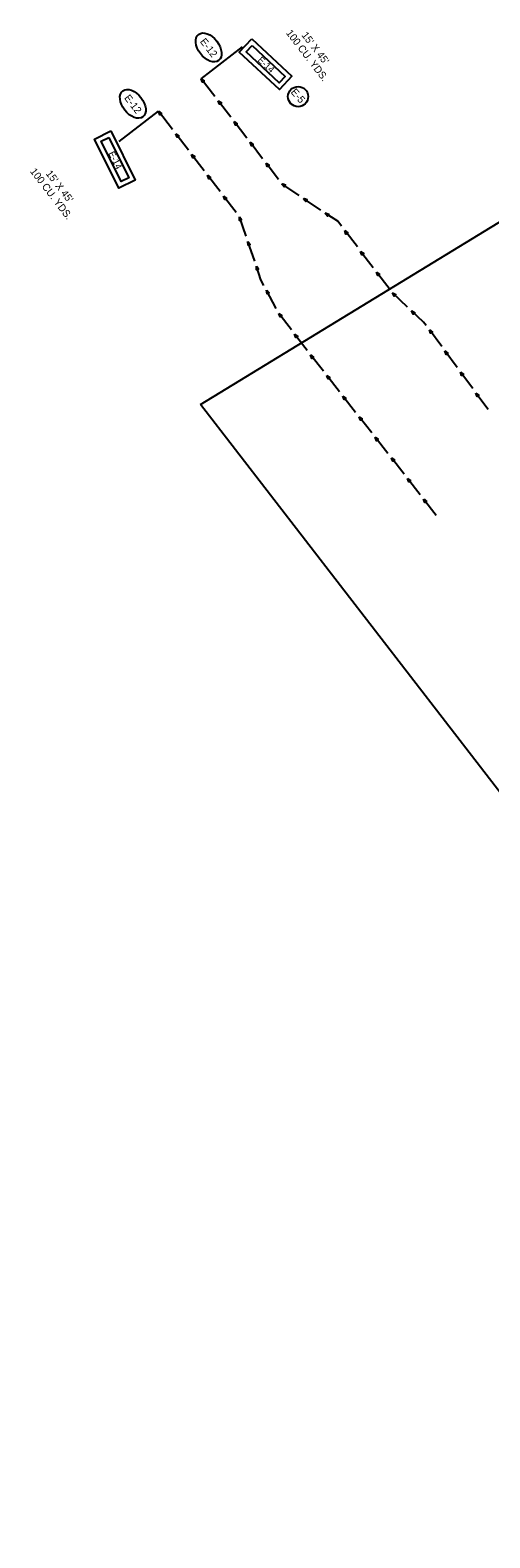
# Model space of a CAD drawing. Extents: x 881727 to 890277, y 1562105 to 1567179.
# Drawn here: x 883424 to 883800, y 1565042 to 1566277 of the extents above; entities that cross this region are included whole.
import ezdxf

# ---------------------------------------------------------------- set-up
doc = ezdxf.new("R2010")
doc.units = 0
for name, color, linetype in [('22', 7, 'Continuous'), ('R_Axis', 7, 'Continuous'), ('R_Proposed Const Limits_Cut', 7, 'Continuous'), ('R_Water', 7, 'Continuous')]:
    doc.layers.add(name, color=color, linetype=linetype)

msp = doc.modelspace()

# ---------------------------------------------------------------- linework, layer by layer
at = {"layer": '22'}
msp.add_lwpolyline([(883563.3, 1565970.3), (883827.9, 1566132), (884540.8, 1565246.7), (884279.1, 1565042.3)], close=True, dxfattribs=at)
at = {"layer": 'R_Proposed Const Limits_Cut'}
for p, q in [((883563.9, 1566237.1), (883597.7, 1566263.1)), ((883565.3, 1566234.6), (883564.2, 1566236.5)), ((883565.1, 1566234.4), (883564.2, 1566236.4)), ((883565.4, 1566234.7), (883564.3, 1566236.5)), ((883566, 1566235.1), (883564.4, 1566236.6)), ((883565.8, 1566235), (883564.4, 1566236.6)), ((883566.1, 1566235.2), (883564.5, 1566236.6)), ((883579, 1566216.3), (883578.1, 1566218.3)), ((883579.4, 1566216.5), (883578.2, 1566218.3)), ((883579.2, 1566216.4), (883578.2, 1566218.3)), ((883579.9, 1566216.9), (883578.3, 1566218.4)), ((883579.7, 1566216.8), (883578.3, 1566218.4)), ((883580.1, 1566217.1), (883578.4, 1566218.5)), ((883496.7, 1566185.6), (883528.9, 1566210.4)), ((883530.3, 1566207.8), (883529.3, 1566209.7)), ((883530.2, 1566207.7), (883529.3, 1566209.7)), ((883530.5, 1566207.9), (883529.4, 1566209.7)), ((883531.2, 1566208.5), (883529.5, 1566209.9)), ((883531, 1566208.3), (883529.5, 1566209.8)), ((883530.9, 1566208.2), (883529.5, 1566209.8)), ((883544.9, 1566189.9), (883543.5, 1566191.4)), ((883545.3, 1566190.1), (883543.6, 1566191.5)), ((883545.1, 1566190), (883543.6, 1566191.5)), ((883592, 1566199.3), (883591.1, 1566201.3)), ((883592.4, 1566199.5), (883591.2, 1566201.3)), ((883592.2, 1566199.4), (883591.2, 1566201.3)), ((883592.8, 1566199.8), (883591.3, 1566201.4)), ((883593.1, 1566200.1), (883591.4, 1566201.5)), ((883592.9, 1566199.9), (883591.4, 1566201.4)), ((883544.2, 1566189.3), (883543.3, 1566191.3)), ((883544.6, 1566189.6), (883543.4, 1566191.4)), ((883544.4, 1566189.5), (883543.4, 1566191.3)), ((883605.3, 1566182.4), (883604.2, 1566184.3)), ((883605.1, 1566182.3), (883604.2, 1566184.3)), ((883605.4, 1566182.5), (883604.3, 1566184.3)), ((883606.1, 1566183.1), (883604.4, 1566184.5)), ((883606, 1566182.9), (883604.4, 1566184.4)), ((883605.8, 1566182.8), (883604.4, 1566184.4)), ((883557.3, 1566172.3), (883556.3, 1566174.3)), ((883557.4, 1566172.5), (883556.4, 1566174.3)), ((883558, 1566172.9), (883556.5, 1566174.4)), ((883557.6, 1566172.6), (883556.5, 1566174.4)), ((883558.3, 1566173.1), (883556.6, 1566174.5)), ((883558.1, 1566173), (883556.6, 1566174.5)), ((883618.3, 1566165.4), (883617.2, 1566167.3)), ((883618.1, 1566165.3), (883617.2, 1566167.3)), ((883618.5, 1566165.5), (883617.3, 1566167.3)), ((883619, 1566165.9), (883617.4, 1566167.4)), ((883618.8, 1566165.8), (883617.4, 1566167.4)), ((883619.2, 1566166.1), (883617.5, 1566167.5)), ((883570.5, 1566155.5), (883569.4, 1566157.4)), ((883570.3, 1566155.3), (883569.4, 1566157.3)), ((883570.6, 1566155.6), (883569.5, 1566157.4)), ((883571.2, 1566156), (883569.6, 1566157.5)), ((883571, 1566155.9), (883569.6, 1566157.5)), ((883571.3, 1566156.1), (883569.7, 1566157.5)), ((883631.9, 1566148.8), (883630.4, 1566150.4)), ((883632.2, 1566149.2), (883630.5, 1566150.5)), ((883632, 1566149), (883630.5, 1566150.4)), ((883632.7, 1566149.9), (883630.6, 1566150.7)), ((883632.5, 1566149.7), (883630.6, 1566150.6)), ((883632.4, 1566149.5), (883630.6, 1566150.6)), ((883583.3, 1566138.3), (883582.4, 1566140.3)), ((883583.7, 1566138.6), (883582.5, 1566140.4)), ((883583.5, 1566138.5), (883582.5, 1566140.4)), ((883584.2, 1566139), (883582.6, 1566140.5)), ((883584, 1566138.9), (883582.6, 1566140.5)), ((883584.4, 1566139.1), (883582.7, 1566140.5)), ((883649.6, 1566136.7), (883648.1, 1566138.3)), ((883649.9, 1566137.1), (883648.2, 1566138.4)), ((883649.7, 1566136.9), (883648.2, 1566138.4)), ((883650.4, 1566137.8), (883648.3, 1566138.6)), ((883650.2, 1566137.7), (883648.3, 1566138.6)), ((883650.1, 1566137.5), (883648.3, 1566138.5)), ((883595.4, 1566121.1), (883595.2, 1566123.3)), ((883595.8, 1566121.2), (883595.3, 1566123.3)), ((883595.6, 1566121.2), (883595.3, 1566123.3)), ((883596.3, 1566121.4), (883595.4, 1566123.3)), ((883596.7, 1566121.5), (883595.5, 1566123.4)), ((883596.5, 1566121.5), (883595.5, 1566123.4)), ((883667.5, 1566125), (883665.9, 1566126.4)), ((883667.4, 1566124.8), (883665.9, 1566126.4)), ((883668, 1566125.7), (883666, 1566126.6)), ((883667.9, 1566125.5), (883666, 1566126.5)), ((883667.6, 1566125.2), (883666, 1566126.4)), ((883668.1, 1566125.9), (883666.1, 1566126.7)), ((883682.7, 1566110.2), (883681.6, 1566112.1)), ((883682.5, 1566110.1), (883681.6, 1566112)), ((883682.8, 1566110.3), (883681.7, 1566112.1)), ((883683.4, 1566110.7), (883681.8, 1566112.2)), ((883683.2, 1566110.6), (883681.8, 1566112.2)), ((883683.5, 1566110.9), (883681.9, 1566112.3)), ((883602.4, 1566100.9), (883602.2, 1566103)), ((883602.9, 1566101), (883602.3, 1566103.1)), ((883602.7, 1566100.9), (883602.3, 1566103)), ((883603.3, 1566101.2), (883602.4, 1566103.1)), ((883603.7, 1566101.3), (883602.5, 1566103.2)), ((883603.5, 1566101.2), (883602.5, 1566103.1)), ((883695.5, 1566093.1), (883694.6, 1566095)), ((883695.9, 1566093.3), (883694.7, 1566095.1)), ((883695.7, 1566093.2), (883694.7, 1566095.1)), ((883696.4, 1566093.7), (883694.8, 1566095.2)), ((883696.2, 1566093.6), (883694.8, 1566095.2)), ((883696.6, 1566093.9), (883694.9, 1566095.3)), ((883609.3, 1566080.6), (883609.1, 1566082.8)), ((883609.6, 1566080.7), (883609.2, 1566082.8)), ((883609.8, 1566080.7), (883609.3, 1566082.8)), ((883610.4, 1566080.9), (883609.4, 1566082.9)), ((883610.2, 1566080.9), (883609.4, 1566082.8)), ((883610.6, 1566081), (883609.5, 1566082.9)), ((883708.5, 1566076.1), (883707.6, 1566078)), ((883708.9, 1566076.3), (883707.7, 1566078.1)), ((883708.7, 1566076.2), (883707.7, 1566078.1)), ((883709.3, 1566076.6), (883707.8, 1566078.2)), ((883709.6, 1566076.9), (883707.9, 1566078.3)), ((883709.4, 1566076.7), (883707.9, 1566078.2)), ((883618.1, 1566061), (883617.5, 1566063.1)), ((883618.5, 1566061.2), (883617.6, 1566063.2)), ((883618.3, 1566061.1), (883617.6, 1566063.1)), ((883618.8, 1566061.4), (883617.7, 1566063.2)), ((883619.2, 1566061.6), (883617.8, 1566063.3)), ((883619, 1566061.5), (883617.8, 1566063.2)), ((883722.1, 1566059.4), (883720.8, 1566061.1)), ((883722, 1566059.3), (883720.8, 1566061.1)), ((883722.6, 1566059.9), (883720.9, 1566061.3)), ((883722.3, 1566059.6), (883720.9, 1566061.2)), ((883722.9, 1566060.2), (883721, 1566061.4)), ((883722.7, 1566060.1), (883721, 1566061.3)), ((883628.7, 1566042.4), (883627.7, 1566044.3)), ((883628.6, 1566042.3), (883627.7, 1566044.2)), ((883628.9, 1566042.5), (883627.8, 1566044.3)), ((883629.6, 1566043.1), (883627.9, 1566044.5)), ((883629.5, 1566042.9), (883627.9, 1566044.4)), ((883629.3, 1566042.8), (883627.9, 1566044.4)), ((883737.4, 1566044.4), (883736.2, 1566046.3)), ((883737.7, 1566044.7), (883736.3, 1566046.4)), ((883737.5, 1566044.6), (883736.3, 1566046.3)), ((883738.2, 1566045.2), (883736.4, 1566046.5)), ((883738, 1566045.1), (883736.4, 1566046.4)), ((883738.3, 1566045.4), (883736.5, 1566046.5)), ((883752.8, 1566029.5), (883751.1, 1566030.9)), ((883641.5, 1566025.2), (883640.6, 1566027.2)), ((883641.9, 1566025.5), (883640.7, 1566027.2)), ((883641.7, 1566025.3), (883640.7, 1566027.2)), ((883642.2, 1566025.7), (883640.8, 1566027.3)), ((883642.6, 1566026), (883640.9, 1566027.4)), ((883642.4, 1566025.9), (883640.9, 1566027.4)), ((883751.7, 1566028.7), (883750.8, 1566030.7)), ((883752.1, 1566029), (883750.9, 1566030.8)), ((883751.9, 1566028.8), (883750.9, 1566030.7)), ((883752.4, 1566029.2), (883751, 1566030.8)), ((883752.6, 1566029.4), (883751.1, 1566030.9)), ((883654.6, 1566008.2), (883653.6, 1566010.2)), ((883654.9, 1566008.5), (883653.7, 1566010.2)), ((883654.7, 1566008.3), (883653.7, 1566010.2)), ((883655.3, 1566008.7), (883653.8, 1566010.3)), ((883655.6, 1566009), (883653.9, 1566010.4)), ((883655.4, 1566008.9), (883653.9, 1566010.3)), ((883764.4, 1566011.5), (883763.5, 1566013.5)), ((883764.8, 1566011.7), (883763.6, 1566013.5)), ((883764.6, 1566011.6), (883763.6, 1566013.5)), ((883765.1, 1566012), (883763.7, 1566013.6)), ((883765.5, 1566012.3), (883763.8, 1566013.7)), ((883765.3, 1566012.1), (883763.8, 1566013.6)), ((883777.1, 1565994.2), (883776.2, 1565996.2)), ((883777.5, 1565994.5), (883776.3, 1565996.3)), ((883777.3, 1565994.4), (883776.3, 1565996.3)), ((883777.8, 1565994.8), (883776.4, 1565996.4)), ((883778.2, 1565995), (883776.5, 1565996.4)), ((883778, 1565994.9), (883776.5, 1565996.4)), ((883668, 1565991.5), (883666.9, 1565993.4)), ((883667.8, 1565991.4), (883666.9, 1565993.3)), ((883668.1, 1565991.6), (883667, 1565993.4)), ((883668.8, 1565992.2), (883667.1, 1565993.5)), ((883668.7, 1565992), (883667.1, 1565993.5)), ((883668.5, 1565991.9), (883667.1, 1565993.5)), ((883681.2, 1565974.6), (883680.1, 1565976.5)), ((883681, 1565974.5), (883680.1, 1565976.5)), ((883681.4, 1565974.8), (883680.2, 1565976.5)), ((883681.9, 1565975.2), (883680.3, 1565976.7)), ((883681.7, 1565975.1), (883680.3, 1565976.6)), ((883682.1, 1565975.3), (883680.4, 1565976.7)), ((883789.8, 1565977), (883788.9, 1565979)), ((883790.2, 1565977.2), (883789, 1565979)), ((883790, 1565977.1), (883789, 1565979)), ((883790.5, 1565977.5), (883789.1, 1565979.1)), ((883790.9, 1565977.8), (883789.2, 1565979.2)), ((883790.7, 1565977.6), (883789.2, 1565979.1)), ((883694.2, 1565957.7), (883693.3, 1565959.6)), ((883694.6, 1565957.9), (883693.4, 1565959.7)), ((883694.4, 1565957.8), (883693.4, 1565959.7)), ((883695.1, 1565958.3), (883693.5, 1565959.8)), ((883694.9, 1565958.2), (883693.5, 1565959.8)), ((883695.3, 1565958.5), (883693.6, 1565959.9)), ((883707.5, 1565940.8), (883706.5, 1565942.8)), ((883707.8, 1565941.1), (883706.6, 1565942.8)), ((883707.6, 1565941), (883706.6, 1565942.8)), ((883708.2, 1565941.4), (883706.7, 1565942.9)), ((883708.5, 1565941.6), (883706.8, 1565943)), ((883708.3, 1565941.5), (883706.8, 1565943)), ((883720.7, 1565924), (883719.7, 1565925.9)), ((883721, 1565924.2), (883719.8, 1565926)), ((883720.9, 1565924.1), (883719.8, 1565926)), ((883721.4, 1565924.5), (883719.9, 1565926.1)), ((883721.7, 1565924.8), (883720, 1565926.2)), ((883721.5, 1565924.6), (883720, 1565926.1)), ((883734.1, 1565907.2), (883733, 1565909.1)), ((883733.9, 1565907.1), (883733, 1565909.1)), ((883734.2, 1565907.4), (883733.1, 1565909.2)), ((883734.9, 1565907.9), (883733.2, 1565909.3)), ((883734.8, 1565907.8), (883733.2, 1565909.3)), ((883734.6, 1565907.7), (883733.2, 1565909.2)), ((883747.2, 1565890.3), (883746.1, 1565892.2)), ((883747, 1565890.2), (883746.1, 1565892.2)), ((883747.3, 1565890.4), (883746.2, 1565892.2)), ((883747.9, 1565890.9), (883746.3, 1565892.3)), ((883747.7, 1565890.7), (883746.3, 1565892.3)), ((883748, 1565891), (883746.4, 1565892.4))]:
    msp.add_line(p, q, dxfattribs=at)
for points in [[(883575.1, 1566222.5), (883563.9, 1566237.1)], [(883588.1, 1566205.5), (883577.8, 1566219)], [(883540.3, 1566195.6), (883528.9, 1566210.4)], [(883553.3, 1566178.6), (883543, 1566192)], [(883601.1, 1566188.5), (883590.8, 1566202)], [(883614.1, 1566171.5), (883603.9, 1566185)], [(883566.3, 1566161.6), (883556, 1566175)], [(883627.2, 1566154.5), (883616.9, 1566168)], [(883579.4, 1566144.6), (883569.1, 1566158)], [(883643.9, 1566141.4), (883629.9, 1566151)], [(883592.4, 1566127.6), (883582.1, 1566141)], [(883661.6, 1566129.4), (883647.6, 1566138.9)], [(883600.7, 1566108.1), (883595.1, 1566124)], [(883675.5, 1566120.3), (883665.3, 1566126.9)], [(883678.5, 1566116.3), (883675.5, 1566120.3)], [(883691.6, 1566099.3), (883681.3, 1566112.7)], [(883607.7, 1566087.8), (883602.1, 1566103.8)], [(883704.6, 1566082.3), (883694.3, 1566095.7)], [(883612.7, 1566072.5), (883609.1, 1566083.5)], [(883615.2, 1566067.8), (883612.7, 1566072.5)], [(883717.6, 1566065.3), (883707.3, 1566078.7)], [(883625.2, 1566048.9), (883617.3, 1566063.9)], [(883732.5, 1566050), (883720.4, 1566061.8)], [(883637.6, 1566031.5), (883627.4, 1566044.9)], [(883745.8, 1566037.6), (883735.8, 1566046.9)], [(883747.8, 1566035), (883745.8, 1566037.6)], [(883760.6, 1566017.8), (883750.5, 1566031.4)], [(883650.5, 1566014.4), (883640.3, 1566027.9)], [(883663.8, 1565997.6), (883653.3, 1566010.9)], [(883773.3, 1566000.6), (883763.2, 1566014.2)], [(883677, 1565980.7), (883666.5, 1565994)], [(883786, 1565983.3), (883775.9, 1565996.9)], [(883690.2, 1565963.9), (883679.8, 1565977.2)], [(883798.6, 1565966.1), (883788.6, 1565979.7)], [(883703.4, 1565947), (883693, 1565960.3)], [(883716.6, 1565930.2), (883706.2, 1565943.5)], [(883729.9, 1565913.3), (883719.4, 1565926.6)], [(883743, 1565896.4), (883732.6, 1565909.8)], [(883756.1, 1565879.5), (883745.8, 1565892.9)]]:
    msp.add_lwpolyline(points, dxfattribs=at)
for points in [[(883563.9, 1566237.1), (883566.3, 1566235.4), (883564.9, 1566234.3)], [(883577.8, 1566219), (883580.3, 1566217.2), (883578.8, 1566216.1)], [(883528.9, 1566210.4), (883531.4, 1566208.6), (883530, 1566207.5)], [(883543, 1566192), (883545.5, 1566190.3), (883544.1, 1566189.2)], [(883590.8, 1566202), (883593.3, 1566200.2), (883591.9, 1566199.1)], [(883603.9, 1566185), (883606.3, 1566183.2), (883604.9, 1566182.1)], [(883556, 1566175), (883558.5, 1566173.3), (883557.1, 1566172.2)], [(883616.9, 1566168), (883619.3, 1566166.2), (883617.9, 1566165.1)], [(883569.1, 1566158), (883571.5, 1566156.3), (883570.1, 1566155.2)], [(883629.9, 1566151), (883632.8, 1566150.1), (883631.8, 1566148.6)], [(883582.1, 1566141), (883584.5, 1566139.3), (883583.1, 1566138.2)], [(883647.6, 1566138.9), (883650.5, 1566138), (883649.5, 1566136.6)], [(883595.1, 1566124), (883596.9, 1566121.6), (883595.2, 1566121)], [(883665.3, 1566126.9), (883668.2, 1566126.1), (883667.3, 1566124.6)], [(883681.3, 1566112.7), (883683.7, 1566111), (883682.3, 1566109.9)], [(883602.1, 1566103.8), (883603.9, 1566101.4), (883602.2, 1566100.8)], [(883694.3, 1566095.7), (883696.8, 1566094), (883695.3, 1566092.9)], [(883609.1, 1566083.5), (883610.8, 1566081.1), (883609.1, 1566080.5)], [(883707.3, 1566078.7), (883709.8, 1566077), (883708.4, 1566075.9)], [(883617.3, 1566063.9), (883619.4, 1566061.7), (883617.9, 1566060.9)], [(883720.4, 1566061.8), (883723, 1566060.4), (883721.8, 1566059.1)], [(883627.4, 1566044.9), (883629.8, 1566043.2), (883628.4, 1566042.1)], [(883735.8, 1566046.9), (883738.5, 1566045.5), (883737.2, 1566044.3)], [(883750.5, 1566031.4), (883753, 1566029.6), (883751.5, 1566028.6)], [(883640.3, 1566027.9), (883642.8, 1566026.1), (883641.3, 1566025.1)], [(883653.3, 1566010.9), (883655.8, 1566009.2), (883654.4, 1566008.1)], [(883763.2, 1566014.2), (883765.7, 1566012.4), (883764.2, 1566011.3)], [(883666.5, 1565994), (883669, 1565992.3), (883667.6, 1565991.2)], [(883775.9, 1565996.9), (883778.4, 1565995.1), (883776.9, 1565994.1)], [(883679.8, 1565977.2), (883682.2, 1565975.5), (883680.8, 1565974.4)], [(883788.6, 1565979.7), (883791.1, 1565977.9), (883789.6, 1565976.8)], [(883693, 1565960.3), (883695.5, 1565958.6), (883694.1, 1565957.5)], [(883706.2, 1565943.5), (883708.7, 1565941.8), (883707.3, 1565940.7)], [(883719.4, 1565926.6), (883721.9, 1565924.9), (883720.5, 1565923.8)], [(883732.6, 1565909.8), (883735.1, 1565908.1), (883733.7, 1565907)], [(883745.8, 1565892.9), (883748.2, 1565891.1), (883746.8, 1565890)]]:
    msp.add_lwpolyline(points, close=True, dxfattribs=at)
for centre in [(883569.9, 1566262.7), (883507.9, 1566216.5)]:
    msp.add_ellipse(centre, major_axis=(8.2, -10.7), ratio=0.622952, dxfattribs=at)
at = {"layer": 'R_Water'}
for points in [[(883605.2, 1566269.8), (883638.1, 1566239.1), (883627.9, 1566228.2), (883595, 1566258.9)], [(883605.4, 1566264.2), (883632.5, 1566238.9), (883627.7, 1566233.8), (883600.7, 1566259.1)], [(883490, 1566194.4), (883509.9, 1566154), (883496.5, 1566147.4), (883476.6, 1566187.7)], [(883488.2, 1566189), (883504.6, 1566155.8), (883498.3, 1566152.8), (883481.9, 1566185.9)]]:
    msp.add_lwpolyline(points, close=True, dxfattribs=at)
msp.add_circle((883643.1, 1566222.4), 8.26, dxfattribs=at)

# ---------------------------------------------------------------- texts
at = {"layer": 'R_Axis'}
for s, p in [('100 CU. YDS.', (883632.9, 1566274.4)), ("15' X 45'", (883645.6, 1566272.6)), ('100 CU. YDS.', (883423.5, 1566161.1)), ("15' X 45'", (883436.3, 1566159.3))]:
    msp.add_text(s, height=6, rotation=307.4724, dxfattribs=at).set_placement(p)
at = {"layer": 'R_Proposed Const Limits_Cut'}
for p in [(883562.5, 1566267.4), (883500.5, 1566221.2)]:
    msp.add_text('E-12', height=6, rotation=307.4724, dxfattribs=at).set_placement(p)
at = {"layer": 'R_Water'}
for s, height, rotation, p in [('E-14', 5.4, 316.9552, (883609.6, 1566251.8)), ('E-5 ', 6, 310.5862, (883636.7, 1566225.9)), ('E-14', 5.4, 296.2811, (883487.7, 1566176))]:
    msp.add_text(s, height=height, rotation=rotation, dxfattribs=at).set_placement(p)

doc.saveas('drawing.dxf')
